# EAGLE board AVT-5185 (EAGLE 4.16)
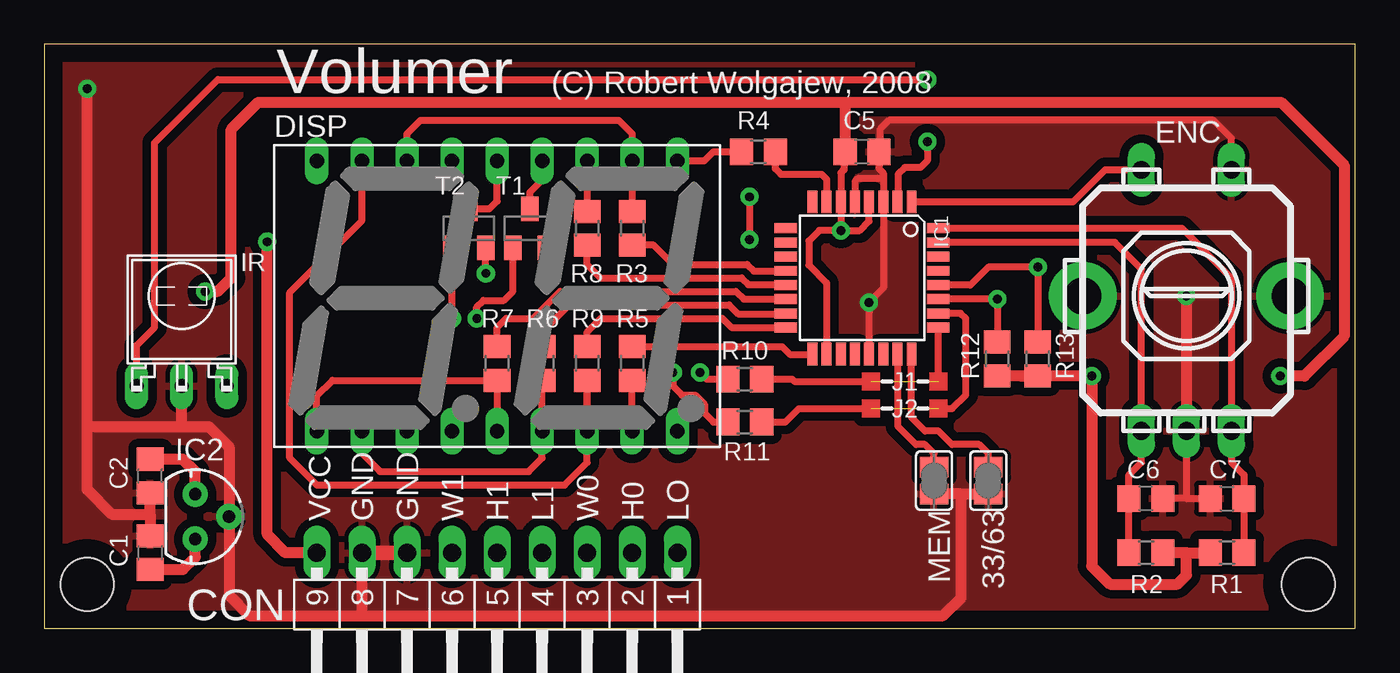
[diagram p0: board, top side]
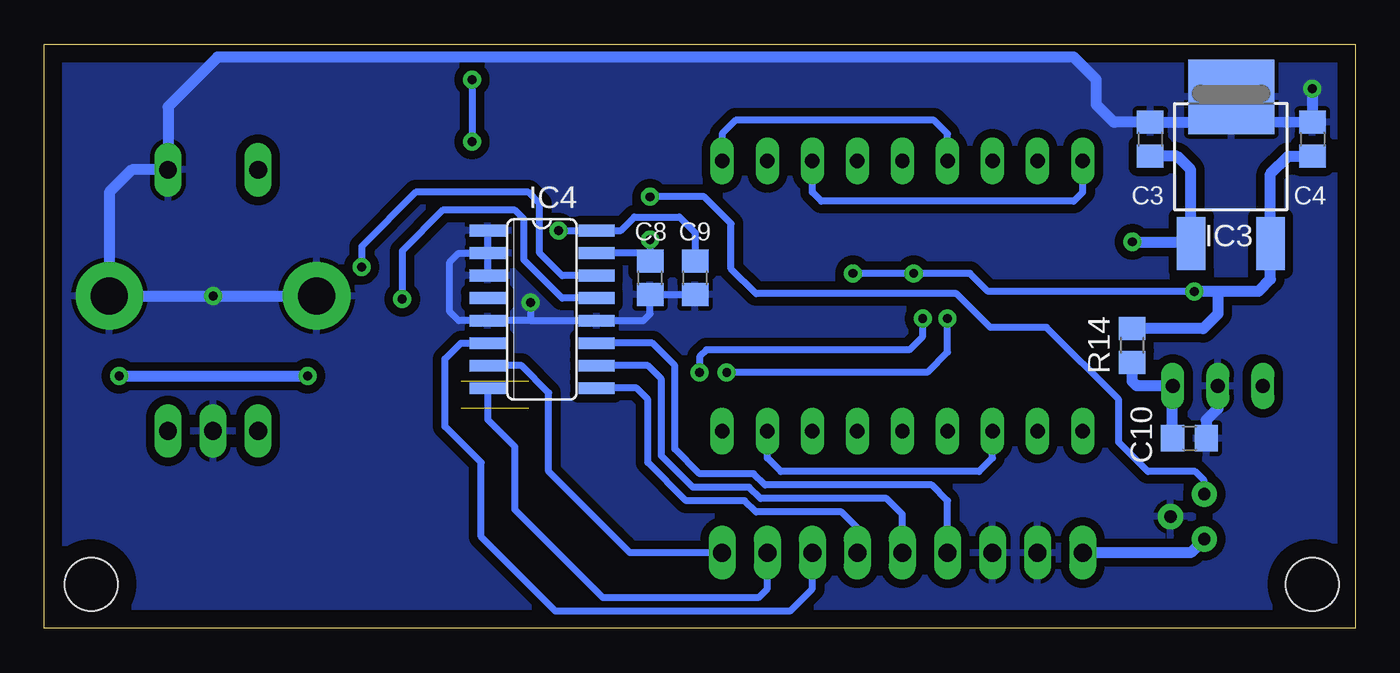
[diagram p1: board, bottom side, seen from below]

Size 73.89 x 32.94 mm. Coordinates in mm from the lower left corner, seen from the top.
Outline: 0,0 73.89,0 73.89,32.94 0,32.94 0,0
Copper layers (1*16): Top 0.035mm / dielectric 1.5mm / Bottom 0.035mm
Design rules "default": minimum track width 10mil, minimum drill 24mil, track to track 8mil, track to pad 8mil, pad to pad 8mil, via to via 8mil, smd to smd 8mil, copper to edge 40mil, drill to drill 8mil, minimum pad ring 10mil, minimum via ring 8mil, stop-mask expansion 4mil, vias tented up to drill 0mil, thermal gap 10mil
Holes 3 mm at 2.41,2.5 71.24,2.5

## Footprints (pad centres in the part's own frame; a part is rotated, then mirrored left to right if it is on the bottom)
SJ = smd 1.168 x 1.6: 1 -0.762,0; 2 0.762,0
C0805 = smd 1.3 x 1.5: 1 -0.95,0; 2 0.95,0
MA09-1W = drill 1.016 long: 1 -10.16,0; 2 -7.62,0; 3 -5.08,0; 4 -2.54,0; 5 0,0; 6 2.54,0; 7 5.08,0; 8 7.62,0; 9 10.16,0
HDSP-R = drill 0.813 long: 1 -10.16,-7.62; 2 -7.62,-7.62; 3 -5.08,-7.62; 4 -2.54,-7.62; 5 0,-7.62; 6 2.54,-7.62; 7 5.08,-7.62; 8 7.62,-7.62; 9 10.16,-7.62; 10 10.16,7.62; 11 7.62,7.62; 12 5.08,7.62; 13 2.54,7.62; 14 0,7.62; 15 -2.54,7.62; 16 -5.08,7.62; 17 -7.62,7.62; 18 -10.16,7.62
ENCODER = drill 1 long: A -2.54,0; B 2.54,0; C 0,0; D -2.54,14.732; E 2.54,14.732 | drill 2.083 pad 3.81 round: CHS1 -5.842,7.62; CHS2 5.842,7.62
TQFP32-08 = smd 1.27 x 0.559: 1 -4.293,2.8; 2 -4.293,2; 3 -4.293,1.2; 4 -4.293,0.4; 5 -4.293,-0.4; 6 -4.293,-1.2; 7 -4.293,-2; 8 -4.293,-2.8; 17 4.293,-2.8; 18 4.293,-2; 19 4.293,-1.2; 20 4.293,-0.4; 21 4.293,0.4; 22 4.293,1.2; 23 4.293,2; 24 4.293,2.8 | smd 0.559 x 1.27: 9 -2.8,-4.293; 10 -2,-4.293; 11 -1.2,-4.293; 12 -0.4,-4.293; 13 0.4,-4.293; 14 1.2,-4.293; 15 2,-4.293; 16 2.8,-4.293; 25 2.8,4.293; 26 2,4.293; 27 1.2,4.293; 28 0.4,4.293; 29 -0.4,4.293; 30 -1.2,4.293; 31 -2,4.293; 32 -2.8,4.293
78LXX = drill 0.7 pad 1.422 round: GND 0,1.905; IN 1.27,0; OUT -1.27,0
DPAK = smd 1.6 x 2.997: 1 -2.261,-4.928; 3 2.21,-4.928 | smd 4.826 x 4.191: 4 0,3.353
SO16 = smd 0.66 x 2.032: 1 -4.445,-3.073; 2 -3.175,-3.073; 3 -1.905,-3.073; 4 -0.635,-3.073; 5 0.635,-3.073; 6 1.905,-3.073; 7 3.175,-3.073; 8 4.445,-3.073; 9 4.445,3.073; 10 3.175,3.073; 11 1.905,3.073; 12 0.635,3.073; 13 -0.635,3.073; 14 -1.905,3.073; 15 -3.175,3.073; 16 -4.445,3.073
SFH5110 = drill 0.8 long: GND 0,-2.54; OUT -2.54,-2.54; VCC 2.54,-2.54
R0805 = smd 1.3 x 1.5: 1 -0.95,0; 2 0.95,0
SOT23-BEC = smd 1 x 1.4: B -0.95,-1.1; C 0,1.1; E 0.95,-1.1

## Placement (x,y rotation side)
33/63  [SJ]  53.21,8.34 270 top
C1  330nF  [C0805]  5.96,4.28 270 top
C2  100nF  [C0805]  5.96,8.6 90 top
C3  330nF  [C0805]  11.55,27.6 270 bottom
C4  100nF  [C0805]  2.41,27.6 270 bottom
C5  100nF  [C0805]  46.1,26.89 180 top
C6  100nF  [C0805]  62.1,7.33 180 top
C7  100nF  [C0805]  66.67,7.33 0 top
C8  100nF  [C0805]  39.75,19.77 90 bottom
C9  100nF  [C0805]  37.21,19.77 90 bottom
C10  100nF  [C0805]  9.34,10.73 0 bottom
CON  [MA09-1W]  25.52,4.28 180 top
DISP  HD-K121  [HDSP-R]  25.52,18.76 0 top
ENC  [ENCODER]  64.38,11.14 0 top
IC1  MEGA8-TQFP32  [TQFP32-08]  46.1,19.77 270 top
IC2  78L05  [78LXX]  8.5,6.31 270 top
IC3  78M05  [DPAK]  6.98,26.63 0 bottom
IC4  DS1881  [SO16]  45.84,18 270 bottom
IR  SFH5110-36  [SFH5110]  7.74,16.22 0 top
MEM  [SJ]  50.16,8.34 270 top
R1  10K  [R0805]  66.67,4.28 180 top
R2  10K  [R0805]  62.1,4.28 0 top
R3  220  [R0805]  33.14,22.57 90 top
R4  220  [R0805]  40.25,26.89 180 top
R5  220  [R0805]  33.14,14.95 270 top
R6  220  [R0805]  28.06,14.95 270 top
R7  220  [R0805]  25.52,14.95 270 top
R8  220  [R0805]  30.6,22.57 90 top
R9  220  [R0805]  30.6,14.95 270 top
R10  2K2  [R0805]  39.49,14.06 180 top
R11  2K2  [R0805]  39.49,11.65 180 top
R12  4K7  [R0805]  53.72,15.2 90 top
R13  4K7  [R0805]  56,15.2 90 top
R14  100  [R0805]  12.57,15.96 270 bottom
T1  BC807-40  [SOT23-BEC]  27.36,22.57 0 top
T2  BC807-40  [SOT23-BEC]  23.93,22.57 0 top

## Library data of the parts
33/63 MEM = jumper
C1-C10 R1-R14 = rcl
CON = con-lstb
DISP = display-hp
ENC = RW_Encoder
IC1 = atmel
IC2 IC3 = v-reg
IC4 = RW_DS1881
IR = RW_SFH5110
T1 T2 = transistor-pnp

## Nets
+3V3: C2.2 C8.2 IC2.OUT IC4.15
+5V: C4.2 C5.2 C9.2 IC1.4 IC1.6 IC1.18 IC3.3 IC4.16 R1.2 R2.2 R12.1 R13.1 R14.1 T1.E T2.E
GND: 33/63.2 C1.1 C2.1 C3.1 C4.1 C5.1 C6.1 C7.1 C8.1 C9.1 C10.2 CON.7 CON.8 ENC.C ENC.CHS1 ENC.CHS2 ENC.E IC1.3 IC1.5 IC1.21 IC2.GND IC3.4 IC4.1 IC4.2 IC4.3 IC4.5 IC4.12 IR.GND MEM.2
N$1: ENC.D IC1.1
N$2: C6.2 ENC.A IC1.31 R2.1
N$3: C7.2 ENC.B IC1.32 R1.1
N$4: IC1.13 R8.1
N$5: IC1.14 R7.1
N$6: IC1.17 R5.1
N$7: IC1.16 R9.1
N$8: IC1.15 R6.1
N$9: IC1.12 R3.1
N$10: DISP.11 DISP.16 R3.2
N$11: DISP.10 DISP.15 R4.2
N$12: DISP.3 DISP.8 R5.2
N$13: DISP.2 DISP.6 R6.2
N$14: DISP.1 DISP.5 R7.2
N$15: DISP.12 DISP.18 R8.2
N$16: DISP.7 DISP.17 R9.2
N$17: IC1.7 R4.1
N$18: DISP.14 T2.C
N$19: DISP.13 T1.C
N$20: IC1.2 IR.OUT
N$21: R10.2 T1.B
N$22: R11.2 T2.B
N$23: IC1.26 R11.1
N$24: IC1.25 R10.1
N$25: CON.6 IC4.11
N$26: CON.5 IC4.10
N$27: C1.2 C3.2 CON.9 IC2.IN IC3.1
N$28: CON.4 IC4.9
N$29: CON.3 IC4.6
N$30: CON.2 IC4.8
N$31: CON.1 IC4.7
N$34: IC1.27 IC4.13 R12.2
N$35: IC1.28 IC4.14 R13.2
N$38: C10.1 IR.VCC R14.2
N$51: IC1.23 MEM.1
N$52: 33/63.1 IC1.24

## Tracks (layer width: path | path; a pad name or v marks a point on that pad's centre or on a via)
+3V3  (via drill 0.5 pad 1.02)
  Top 0.406: v39.75,24.35 v39.75,21.93
  Top 0.61: C2.2 7.81,9.55 8.5,8.85 IC2.OUT
  Bottom 0.406: C8.2 40.19,21.17 IC4.15 | IC2.OUT 8.5,8.34 9.01,8.85 11.68,8.85 13.33,10.5 13.33,12.92 17.39,16.98 20.57,16.98 22.47,18.88 33.78,18.88 35.17,20.28 35.17,22.82 36.7,24.35 v39.75,24.35 | C8.2 39.75,20.66 | v39.75,21.93 C8.2
+5V  (via drill 0.5 pad 1.02)
  Top 0.406: C5.2 45.08,26.89 45.08,25.87 44.9,25.69 IC1.6 v44.9,22.44 | T1.E v28.31,20.03 v28.32,20.03 | T2.E 24.88,21.45 24.89,21.45 v24.89,20.03 | IC1.4 46.5,22.97 45.97,22.44 v44.9,22.44 | IC1.18 44.1,19.49 43.1,20.48 43.1,21.86 43.68,22.44 v44.9,22.44
  Top 0.61: C5.2 45.14,29.68 | 45.14,29.68 12.06,29.68 10.54,28.16 10.54,19.77 9.77,19.01 v9.08,19.01 9.27,19.01 | 45.14,29.68 69.72,29.68 73.27,26.12 73.27,16.47 71.04,14.24 v69.67,14.24 | 54.99,14.25 R13.1 | 54.99,14.25 59.04,14.25 v59.05,14.24 59.05,3.52 60.07,2.5 63.88,2.5 64.38,3.01 64.38,4.28 | 53.72,14.26 R12.1 54.99,14.25 | 65.78,4.28 R1.2 64.38,4.28 | 64.38,4.28 R2.2
  Bottom 0.406: v28.32,20.03 v24.89,20.03 24.89,20.05 24.86,20.03 21.71,20.03 20.7,19.01 v9.08,19.01 | v44.9,22.44 42.79,22.44 | C9.2 37.21,22.31 38.09,23.2 40.63,23.2 41.4,22.44 42.79,22.44 | 42.79,22.44 IC4.16
  Bottom 0.61: 7.74,19.01 5.46,19.01 4.77,19.7 4.77,21.76 | 7.74,19.01 v9.08,19.01 | v69.67,14.24 v59.05,14.24 | 4.77,21.76 IC3.3 | 4.77,21.76 4.77,25.64 3.78,26.63 2.48,26.63 2.47,26.65 C4.2 | R14.1 8.57,16.91 7.74,17.74 7.74,19.01
GND  (via drill 0.5 pad 1.02)
  Top 0.406: 64.38,7.33 C6.1 | 64.38,7.33 C7.1 | ENC.C 64.38,7.33 | 47.3,25.36 47.3,25.69 47.05,25.93 47.05,26.82 47.05,26.83 C5.1 47.11,26.89 47.11,28.16 47.62,28.66 65.91,28.66 66.92,27.65 ENC.E | 47.3,25.36 IC1.3 | IC1.5 45.7,25.22 45.84,25.36 47.3,25.36 | 47.37,24.09 47.34,24.07 IC1.3 | IC1.3 47.29,19.19 v46.48,18.38 46.5,18.36 46.5,15.5 | 46.5,15.5 46.5,15.51 | 46.5,15.5 IC1.21
  Top 0.61: 51.68,7.58 MEM.2 | v64.38,18.76 ENC.C | 5.96,6.44 C1.1 | 5.96,6.44 C2.1 | 17.9,0.72 11.55,0.72 10.41,1.87 IC2.GND 10.41,10.25 9.27,11.39 7.74,11.39 | 17.9,0.72 CON.8 | 2.41,11.39 7.74,11.39 | 2.41,11.39 2.41,7.84 3.8,6.44 5.96,6.44 | 7.74,11.39 IR.GND | 2.41,11.39 v2.41,30.44 | 51.68,7.58 51.68,1.74 50.67,0.72 17.9,0.72 | 51.68,7.58 33/63.2
  Top 0.813: CON.8 CON.7
  Bottom 0.406: IC4.1 48.89,22.44 48.89,21.17 | 48.89,19.9 IC4.3 48.91,21.15 48.89,21.17 | 37.18,18.81 C9.1 39.68,18.82 39.69,18.82 C8.1 39.75,17.74 40.13,17.36 IC4.12 46.48,17.36 | 46.48,17.36 48.89,17.36 | 48.89,17.36 IC4.5 | 48.89,17.36 50.54,17.36 51.05,17.87 51.05,20.66 50.54,21.17 IC4.2 48.89,21.17 | v46.48,18.38 46.48,17.36
  Bottom 0.61: ENC.CHS1 v64.38,18.76 ENC.CHS2 70.23,24.6 68.96,25.87 ENC.E 66.92,29.43 64.13,32.22 15.87,32.22 14.6,30.95 14.6,29.55 13.58,28.54 13.57,28.55 C3.1 | C4.1 6.98,28.54 | 6.98,28.54 | 6.98,28.54 IC3.4 | C4.1 2.41,28.41 | v2.41,30.44 C4.1 | C3.1 11.55,28.66 | 11.49,28.54 C3.1 | C3.1 11.43,28.55 11.43,28.54 11.42,28.54 6.98,28.54 | C10.2 8.39,11.76 7.74,12.41 IR.GND
  pour Top (isolate 0.483): 0.12,32.73 73.53,32.73 73.53,0.22 0.12,0.22
  pour Bottom (isolate 0.483): 0.12,32.73 73.53,32.73 73.53,0.22 0.12,0.22
N$1
  Top 0.406: IC1.1 58.01,24.07 59.81,25.87 ENC.D
N$2
  Top 0.406: R2.1 61.15,4.34 61.15,4.35 C6.2 61.15,8.66 61.84,9.36 ENC.A 61.84,20.28 60.35,21.77 IC1.31
N$3
  Top 0.406: R1.1 C7.2 67.62,8.66 66.92,9.36 ENC.B 66.92,19.77 64.12,22.57 IC1.32
N$4
  Top 0.406: 41.78,19.39 IC1.13 41.73,19.37 41.71,19.39 39.68,19.39 39.3,19.77 31.36,19.77 30.6,20.54 R8.1
N$5
  Top 0.406: IC1.14 41.78,18.57 39.43,18.57 38.98,19.01 29.08,19.01 27.55,17.49 26.03,17.49 25.52,16.98 R7.1
N$6
  Top 0.406: R5.1 41.59,15.9 42.03,15.46 43.3,15.46 IC1.17
N$7
  Top 0.406: R9.1 30.6,16.73 31.36,17.49 38.22,17.49 38.73,16.98 41.78,16.98 41.78,16.97 IC1.16
N$8
  Top 0.406: R6.1 28.06,16.73 29.59,18.25 38.6,18.25 39.11,17.74 41.71,17.74 41.75,17.77 IC1.15
N$9
  Top 0.406: R3.1 34.35,21.62 35.43,20.54 39.62,20.54 40,20.16 41.78,20.16 IC1.12
N$10
  Top 0.406: R3.2 DISP.11 33.14,27.9 32.38,28.66 21.2,28.66 20.44,27.9 DISP.16
N$11
  Top 0.406: DISP.10 37.21,26.38 37.71,26.89 R4.2
  Bottom 0.406: DISP.15 22.98,27.9 23.74,28.66 34.92,28.66 35.68,27.9 DISP.10
N$12
  Top 0.406: DISP.8 R5.2
  Bottom 0.406: DISP.3 20.44,9.61 21.2,8.85 32.38,8.85 33.14,9.61 DISP.8
N$13
  Top 0.406: R6.2 DISP.6 28.06,9.61 27.3,8.85 18.92,8.85 17.9,9.87 DISP.2
N$14
  Top 0.406: R7.2 DISP.5 | DISP.1 15.36,13.11 16.25,14 R7.2 | R7.2
N$15
  Top 0.406: DISP.12 R8.2
  Bottom 0.406: DISP.18 15.36,24.6 15.87,24.09 30.09,24.09 30.6,24.6 DISP.12
N$16
  Top 0.406: DISP.7 R9.2 30.6,9.36 29.33,8.09 15.36,8.09 13.84,9.61 13.84,18.95 17.9,23.01 DISP.17
N$17
  Top 0.406: IC1.7 44.1,25.33 43.81,25.62 41.52,25.62 41.21,25.93 R4.1
N$18
  Top 0.406: T2.C 25.1,23.67 25.52,24.09 DISP.14
N$19
  Top 0.406: DISP.13 28.06,25.29 27.38,24.6 27.38,23.69 T1.C
N$20  (via drill 0.5 pad 1.02)
  Top 0.406: IR.OUT 5.2,15.96 6.22,16.98 6.22,27.39 9.77,30.95 v49.78,30.95 | IC1.2 48.13,24.09 48.13,25.62 48.51,26 49.4,26 49.78,26.38 v49.78,27.46
  Bottom 0.406: v49.78,30.95 v49.78,27.46
N$21  (via drill 0.5 pad 1.02)
  Top 0.406: 26.44,21.48 26.43,21.47 T1.B 26.41,21.45 26.41,19.01 25.9,18.5 24.76,18.5 24.38,18.12 v24.38,17.49 | R10.2 37.33,14.06 v36.95,14.44
  Bottom 0.406: v24.38,17.49 24.38,16.47 25.14,15.71 36.57,15.71 36.95,15.33 v36.95,14.44
N$22  (via drill 0.5 pad 1.02)
  Top 0.406: T2.B 22.99,21.45 22.98,21.45 v22.98,17.49 | R11.2 37.71,11.65 37.21,12.15 37.21,12.66 36.7,13.17 35.94,13.17 35.43,13.68 v35.43,14.44
  Bottom 0.406: v35.43,14.44 24.12,14.44 22.98,15.58 v22.98,17.49
N$23  (1 unrouted)
  Top 0.406: IC1.26 51.65,17.77 51.94,17.49 51.94,13.17 51.18,12.41 50.41,12.41 | R11.1 41.78,11.65 42.54,12.41 46.6,12.41
N$24  (1 unrouted)
  Top 0.406: 50.39,13.93 IC1.25 | R10.1 42.16,14.06 42.29,13.93 46.6,13.93
N$25
  Bottom 0.406: CON.6 22.98,7.2 23.87,8.09 33.27,8.09 33.9,8.73 36.95,8.73 38.35,10.12 38.35,14.82 39.62,16.09 IC4.11
N$26
  Bottom 0.406: CON.5 25.52,6.44 26.41,7.33 33.52,7.33 34.16,7.96 37.33,7.96 39.11,9.74 39.11,14.06 39.87,14.82 IC4.10 42.79,14.82
N$27  (via drill 0.5 pad 1.02)
  Top 0.61: C1.2 7.81,3.33 8.5,4.03 IC2.IN | v12.57,21.81 12.57,5.3 13.58,4.28 CON.9
  Bottom 0.61: 9.27,21.81 9.24,21.78 IC3.1 | v12.57,21.81 9.27,21.81 | CON.9 9.27,4.28 IC2.IN | 9.27,21.81 9.27,25.87 10.03,26.63 11.55,26.63 C3.2
N$28
  Bottom 0.406: CON.4 28.06,5.68 28.95,6.57 33.78,6.57 34.41,7.2 37.71,7.2 39.87,9.36 39.87,12.92 40.51,13.55 IC4.9
N$29
  Bottom 0.406: CON.3 30.6,2.25 31.87,0.98 45.08,0.98 49.27,5.17 49.27,9.36 51.3,11.39 51.3,15.2 50.41,16.09 IC4.6 48.89,16.09
N$30
  Bottom 0.406: CON.2 33.14,2.25 33.65,1.74 42.41,1.74 47.37,6.69 47.37,10.25 48.89,11.77 48.89,13.42 48.91,13.45 IC4.8
N$31
  Bottom 0.406: CON.1 40.89,4.28 45.46,8.85 45.46,13.3 46.98,14.82 IC4.7
N$34  (via drill 0.5 pad 1.02)
  Top 0.406: R12.2 v53.72,18.58 v53.72,18.57 IC1.27
  Bottom 0.406: v53.72,18.58 53.72,21.3 51.43,23.58 47.37,23.58 46.86,23.08 46.86,20.79 44.7,18.63 IC4.13
N$35  (via drill 0.5 pad 1.02)
  Top 0.406: R13.2 v56,20.38 53.21,20.38 52.19,19.37 50.41,19.37 IC1.28
  Bottom 0.406: v56,20.38 56,21.55 52.95,24.6 46.6,24.6 45.97,23.97 45.97,21.17 44.7,19.9 IC4.14
N$38
  Bottom 0.61: C10.1 IR.VCC 12.31,13.68 12.57,13.93 R14.2
N$51
  Top 0.406: IC1.23 48.13,15.46 48.13,11.39 49.14,10.38 49.65,10.38 50.16,9.87 MEM.1
N$52
  Top 0.406: IC1.24 48.9,15.46 48.89,15.46 48.89,11.9 49.65,11.14 50.41,11.14 51.18,10.38 52.7,10.38 53.21,9.87 33/63.1
(copper drawn outside any net)
  shapes: Top area x4

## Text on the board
tNames: Volumer | (C) Robert Wolgajew, 2008 | J1 | J2 | VCC | GND | GND | W1 | H1 | L1 | W0 | H0 | LO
